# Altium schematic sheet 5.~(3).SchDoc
size 420 x 297 mm
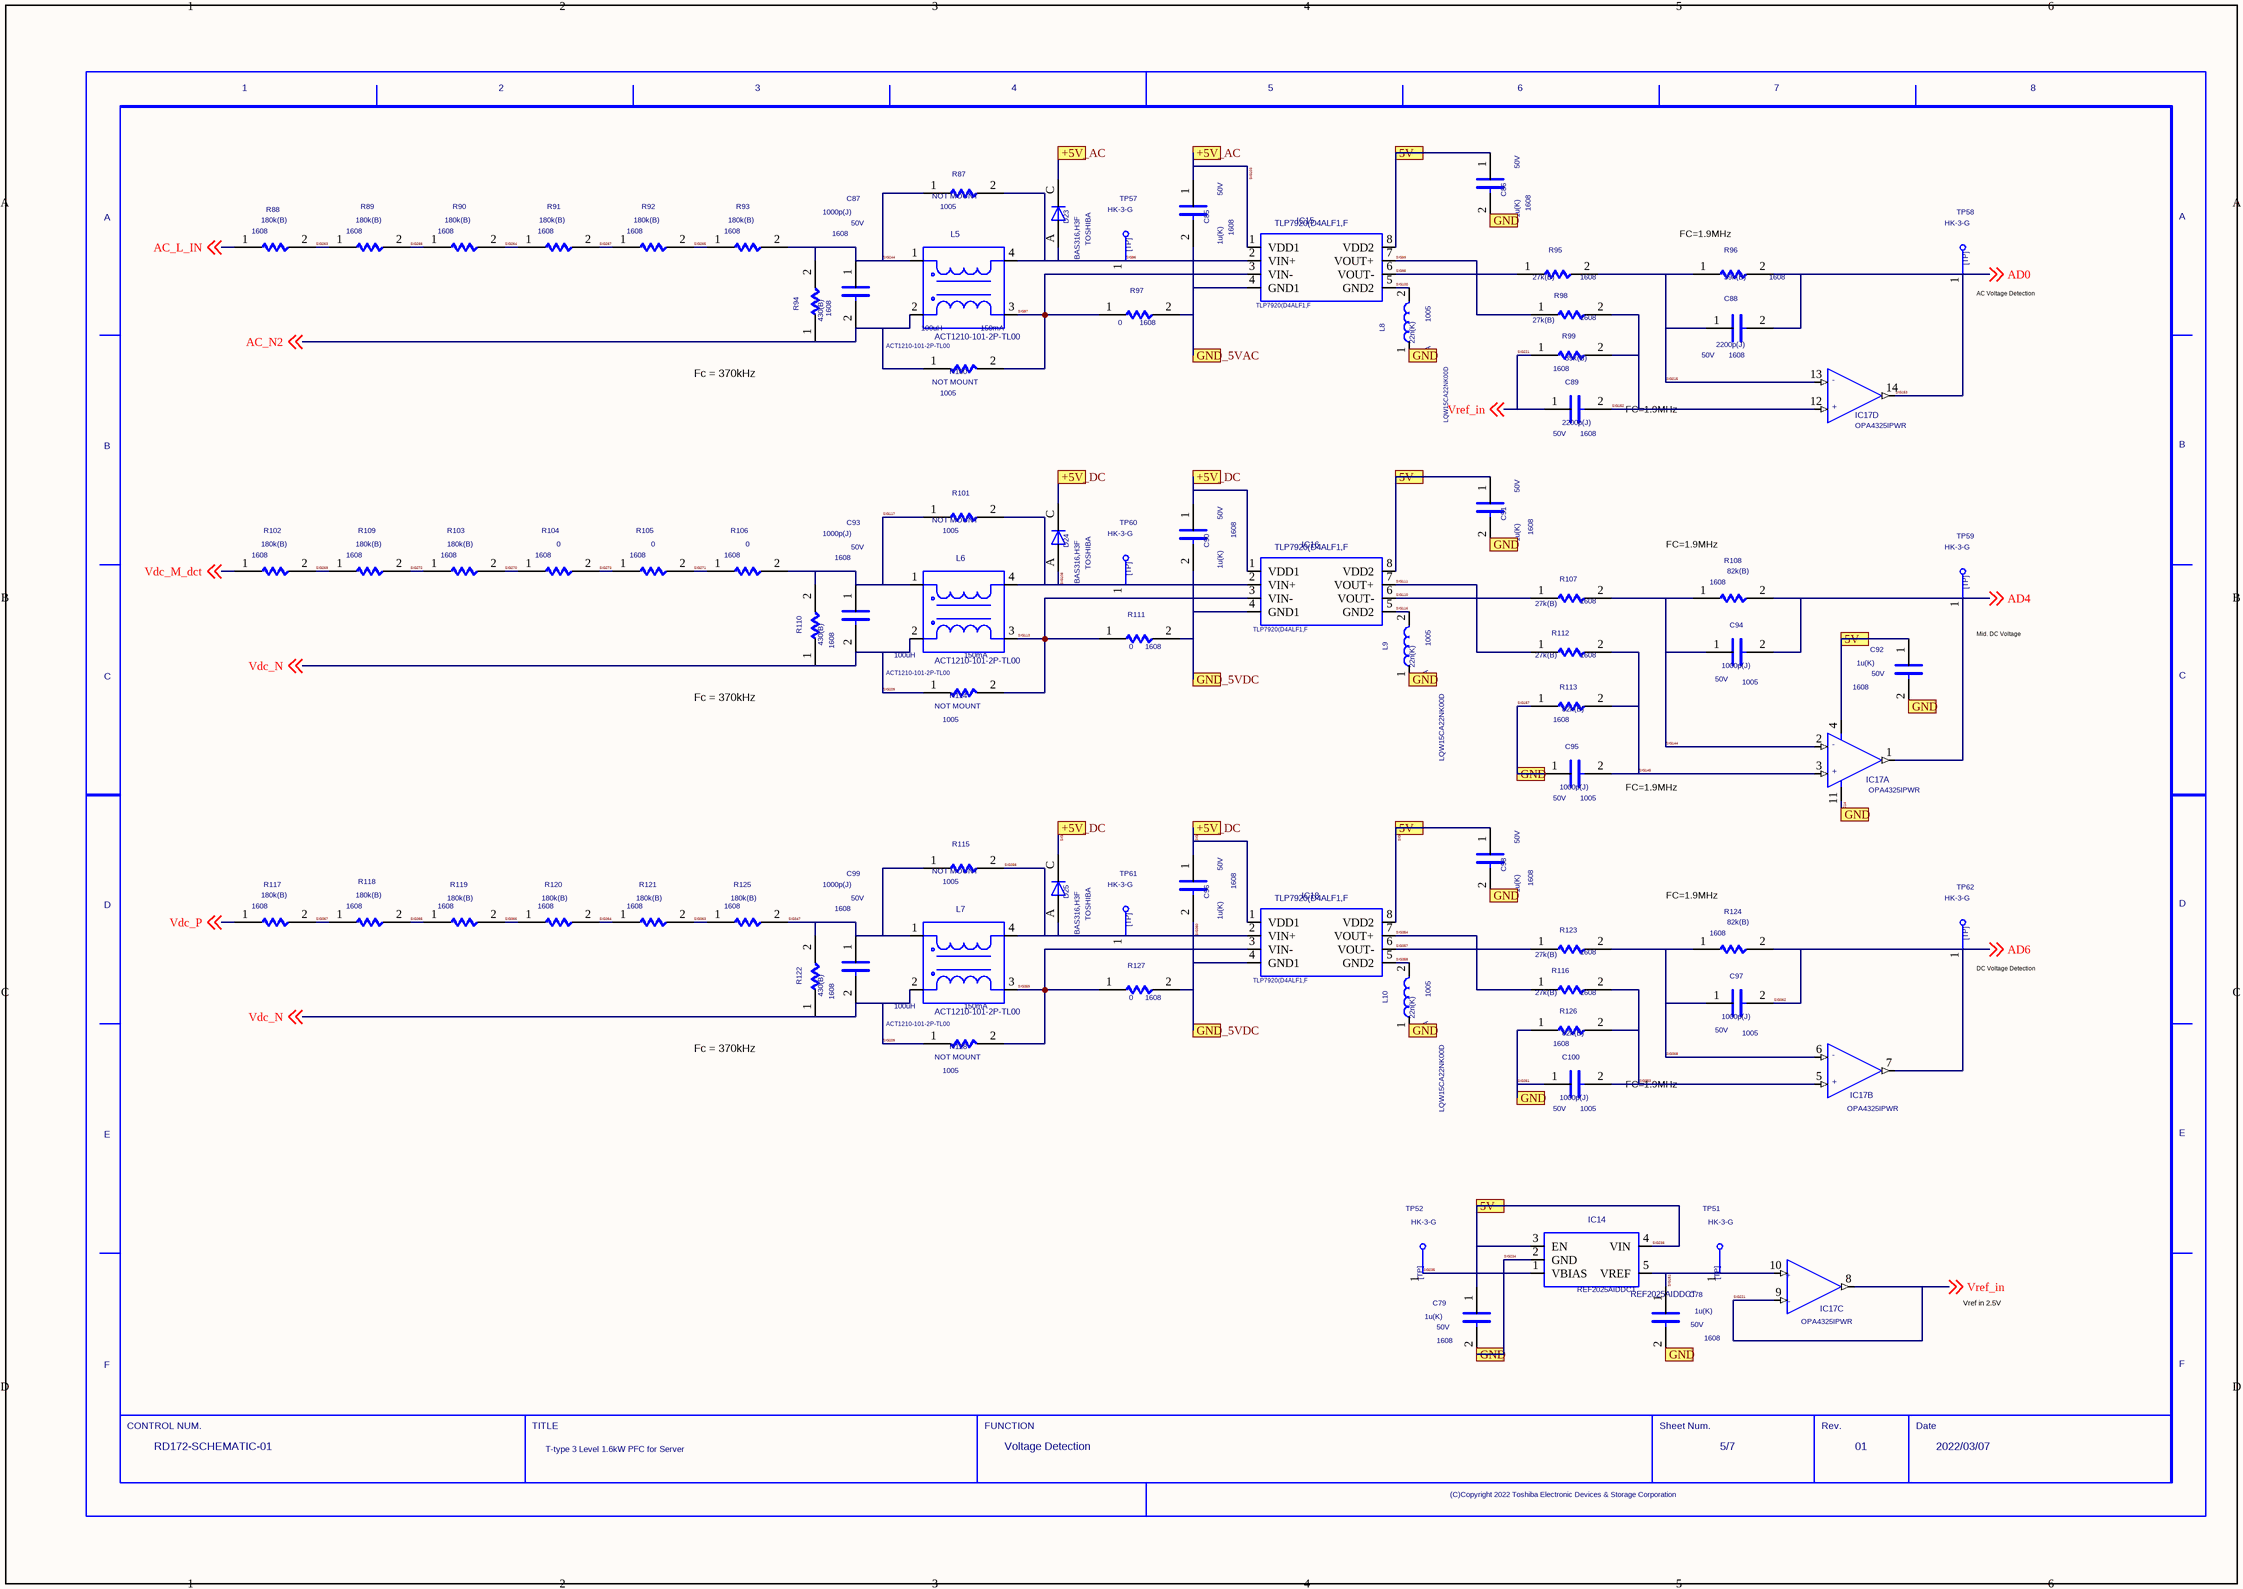
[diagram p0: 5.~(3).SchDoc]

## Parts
C78  SIZECODESMD: 1608  VAL2: 50V  VAL1: 1u(K)  (hidden comment: C)
C79  SIZECODESMD: 1608  VAL2: 50V  VAL1: 1u(K)  (hidden comment: C)
C85  SIZECODESMD: 1608  VAL2: 50V  VAL1: 1u(K)  (hidden comment: C)
C86  SIZECODESMD: 1608  VAL2: 50V  VAL1: 1u(K)  (hidden comment: C)
C87  SIZECODESMD: 1608  VAL2: 50V  VAL1: 1000p(J)  (hidden comment: C)
C88  SIZECODESMD: 1608  VAL2: 50V  VAL1: 2200p(J)  (hidden comment: C)
C89  SIZECODESMD: 1608  VAL2: 50V  VAL1: 2200p(J)  (hidden comment: C)
C90  SIZECODESMD: 1608  VAL2: 50V  VAL1: 1u(K)  (hidden comment: C)
C91  SIZECODESMD: 1608  VAL2: 50V  VAL1: 1u(K)  (hidden comment: C)
C92  SIZECODESMD: 1608  VAL2: 50V  VAL1: 1u(K)  (hidden comment: C)
C93  SIZECODESMD: 1608  VAL2: 50V  VAL1: 1000p(J)  (hidden comment: C)
C94  SIZECODESMD: 1005  VAL2: 50V  VAL1: 1000p(J)  (hidden comment: C)
C95  SIZECODESMD: 1005  VAL2: 50V  VAL1: 1000p(J)  (hidden comment: C)
C96  SIZECODESMD: 1608  VAL2: 50V  VAL1: 1u(K)  (hidden comment: C)
C97  SIZECODESMD: 1005  VAL2: 50V  VAL1: 1000p(J)  (hidden comment: C)
C98  SIZECODESMD: 1608  VAL2: 50V  VAL1: 1u(K)  (hidden comment: C)
C99  SIZECODESMD: 1608  VAL2: 50V  VAL1: 1000p(J)  (hidden comment: C)
C100  SIZECODESMD: 1005  VAL2: 50V  VAL1: 1000p(J)  (hidden comment: C)
D23  USERCOMPTEXT3: TOSHIBA  VAL3: BAS316,H3F  (hidden comment: D)
D24  USERCOMPTEXT3: TOSHIBA  VAL3: BAS316,H3F  (hidden comment: D)
D25  USERCOMPTEXT3: TOSHIBA  VAL3: BAS316,H3F  (hidden comment: D)
IC14  REF2025AIDDCT
IC15  TLP7920(D4ALF1,F
IC16  TLP7920(D4ALF1,F
IC17  VAL3: OPA4325IPWR  (hidden comment: OPA4325IPWR_4)  (parts A,B,C,D of 4)
IC18  TLP7920(D4ALF1,F
L5  ACT1210-101-2P-TL00  VAL1: 100uH
L6  ACT1210-101-2P-TL00  VAL1: 100uH
L7  ACT1210-101-2P-TL00  VAL1: 100uH
L8  VAL3: LQW15CA22NK00D  VAL2: 1.3A  VAL1: 22n(K)  SIZECODESMD: 1005  (hidden comment: L)
L9  VAL3: LQW15CA22NK00D  VAL2: 1.3A  VAL1: 22n(K)  SIZECODESMD: 1005  (hidden comment: L)
L10  VAL3: LQW15CA22NK00D  VAL2: 1.3A  VAL1: 22n(K)  SIZECODESMD: 1005  (hidden comment: L)
R87  SIZECODESMD: 1005  NOTMOUNT: NOT MOUNT  (hidden comment: R)
R88  SIZECODESMD: 1608  VAL1: 180k(B)  (hidden comment: R)
R89  SIZECODESMD: 1608  VAL1: 180k(B)  (hidden comment: R)
R90  SIZECODESMD: 1608  VAL1: 180k(B)  (hidden comment: R)
R91  SIZECODESMD: 1608  VAL1: 180k(B)  (hidden comment: R)
R92  SIZECODESMD: 1608  VAL1: 180k(B)  (hidden comment: R)
R93  SIZECODESMD: 1608  VAL1: 180k(B)  (hidden comment: R)
R94  SIZECODESMD: 1608  VAL1: 430(B)  (hidden comment: R)
R95  SIZECODESMD: 1608  VAL1: 27k(B)  (hidden comment: R)
R96  SIZECODESMD: 1608  VAL1: 39k(B)  (hidden comment: R)
R97  SIZECODESMD: 1608  VAL1: 0  (hidden comment: R)
R98  SIZECODESMD: 1608  VAL1: 27k(B)  (hidden comment: R)
R99  SIZECODESMD: 1608  VAL1: 39k(B)  (hidden comment: R)
R100  SIZECODESMD: 1005  NOTMOUNT: NOT MOUNT  (hidden comment: R)
R101  SIZECODESMD: 1005  NOTMOUNT: NOT MOUNT  (hidden comment: R)
R102  SIZECODESMD: 1608  VAL1: 180k(B)  (hidden comment: R)
R103  SIZECODESMD: 1608  VAL1: 180k(B)  (hidden comment: R)
R104  SIZECODESMD: 1608  VAL1: 0  (hidden comment: R)
R105  SIZECODESMD: 1608  VAL1: 0  (hidden comment: R)
R106  SIZECODESMD: 1608  VAL1: 0  (hidden comment: R)
R107  SIZECODESMD: 1608  VAL1: 27k(B)  (hidden comment: R)
R108  SIZECODESMD: 1608  VAL1: 82k(B)  (hidden comment: R)
R109  SIZECODESMD: 1608  VAL1: 180k(B)  (hidden comment: R)
R110  SIZECODESMD: 1608  VAL1: 430(B)  (hidden comment: R)
R111  SIZECODESMD: 1608  VAL1: 0  (hidden comment: R)
R112  SIZECODESMD: 1608  VAL1: 27k(B)  (hidden comment: R)
R113  SIZECODESMD: 1608  VAL1: 82k(B)  (hidden comment: R)
R114  SIZECODESMD: 1005  NOTMOUNT: NOT MOUNT  (hidden comment: R)
R115  SIZECODESMD: 1005  NOTMOUNT: NOT MOUNT  (hidden comment: R)
R116  SIZECODESMD: 1608  VAL1: 27k(B)  (hidden comment: R)
R117  SIZECODESMD: 1608  VAL1: 180k(B)  (hidden comment: R)
R118  SIZECODESMD: 1608  VAL1: 180k(B)  (hidden comment: R)
R119  SIZECODESMD: 1608  VAL1: 180k(B)  (hidden comment: R)
R120  SIZECODESMD: 1608  VAL1: 180k(B)  (hidden comment: R)
R121  SIZECODESMD: 1608  VAL1: 180k(B)  (hidden comment: R)
R122  SIZECODESMD: 1608  VAL1: 430(B)  (hidden comment: R)
R123  SIZECODESMD: 1608  VAL1: 27k(B)  (hidden comment: R)
R124  SIZECODESMD: 1608  VAL1: 82k(B)  (hidden comment: R)
R125  SIZECODESMD: 1608  VAL1: 180k(B)  (hidden comment: R)
R126  SIZECODESMD: 1608  VAL1: 82k(B)  (hidden comment: R)
R127  SIZECODESMD: 1608  VAL1: 0  (hidden comment: R)
R128  SIZECODESMD: 1005  NOTMOUNT: NOT MOUNT  (hidden comment: R)
TP51  VAL3: HK-3-G  (hidden comment: TP)
TP52  VAL3: HK-3-G  (hidden comment: TP)
TP57  VAL3: HK-3-G  (hidden comment: TP)
TP58  VAL3: HK-3-G  (hidden comment: TP)
TP59  VAL3: HK-3-G  (hidden comment: TP)
TP60  VAL3: HK-3-G  (hidden comment: TP)
TP61  VAL3: HK-3-G  (hidden comment: TP)
TP62  VAL3: HK-3-G  (hidden comment: TP)
U?  DATE: 2022/03/07  REVISION: 01  SHEETNUMBER: 5/7  FUNCTION: Voltage Detection  TITLE: T-type 3 Level 1.6kW PFC for Server  DRAWINGNUMBER: RD172-SCHEMATIC-01  (hidden comment: WAKU_DEF100)

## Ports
5V, +5V_AC, +5V_DC, GND, GND_5VAC, GND_5VDC

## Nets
AC_L_IN: R88.1 ; off-sheet AC_L_IN
AC_N2: C87.2 L5.2 R94.1 R100.1 ; off-sheet AC_N2
AD4: C94.2 IC17.1(OUT) R108.2 TP59.1 ; off-sheet AD4
GND_5VAC: C85.2 IC15.4(GND1) R97.2 ; port GND_5VAC
SIG96: D23.A IC15.2(VIN+) L5.4 R87.2 TP57.1
SIG97: IC15.3(VIN-) L5.3 R97.1 R100.2
SIG98: IC15.6(VOUT-) R95.1
SIG99: IC15.7(VOUT+) R98.1
SIG100: IC15.5(GND2) L8.2
SIG103: C85.1 D23.C IC15.1(VDD1) ; port +5V_AC
SIG108: D24.A IC16.2(VIN+) L6.4 R101.2 TP60.1
SIG110: IC16.6(VOUT-) R107.1
SIG111: IC16.7(VOUT+) R112.1
SIG113: IC16.3(VIN-) L6.3 R111.1 R114.2
SIG116: IC16.5(GND2) L9.2
SIG117: C93.1 L6.1 R101.1 R106.2 R110.2
SIG144: C94.1 IC17.2(IN-) R107.2 R108.1
SIG145: C95.2 IC17.3(IN+) R112.2 R113.2
SIG151: C78.1 IC14.5(VREF) IC17.10 TP51.1
SIG152: C89.2 IC17.12 R98.2 R99.2
SIG153: C88.2 IC17.14 R96.2 TP58.1 ; off-sheet AD0  [also labelled AD0]
SIG157: C78.2 C79.2 C86.2 C91.2 C92.2 C95.1 C98.2 C100.1 IC14.2(GND) IC17.11(V-) L8.1 L9.1 L10.1 R113.1 R126.1 ; port GND  [also labelled SIG214, SIG234, SIG351]
SIG209: C93.2 C99.2 L6.2 L7.2 R110.1 R114.1 R122.1 R128.1 ; off-sheet Vdc_N  [also labelled Vdc_N]
SIG215: C88.1 IC17.13 R95.2 R96.1
SIG221: C89.1 IC17.8 IC17.9 R99.1 ; off-sheet Vref_in  [also labelled Vref_in]
SIG235: IC14.1(VBIAS) TP52.1
SIG236: C79.1 C86.1 C91.1 C92.1 C98.1 IC14.3(EN) IC14.4(VIN) IC15.8(VDD2) IC16.8(VDD2) IC17.4(V+) IC18.8(VDD2) ; port 5V  [also labelled SIG349]
SIG244: C87.1 L5.1 R87.1 R93.2 R94.2
SIG263: R88.2 R89.1
SIG264: R90.2 R91.1
SIG265: R92.2 R93.1
SIG266: R89.2 R90.1
SIG267: R91.2 R92.1
SIG269: R102.2 R109.1
SIG270: R103.2 R104.1
SIG271: R105.2 R106.1
SIG272: R103.1 R109.2
SIG273: R104.2 R105.1
SIG347: C99.1 L7.1 R115.1 R122.2 R125.2
SIG353: C100.2 IC17.5 R116.2 R126.2
SIG354: IC18.7(VOUT+) R116.1
SIG355: C90.1 C96.1 D24.C D25.C IC16.1(VDD1) IC18.1(VDD1) ; port +5V_DC  [also labelled SIG361]
SIG356: D25.A IC18.2(VIN+) L7.4 R115.2 TP61.1
SIG357: IC18.6(VOUT-) R123.1
SIG358: IC18.5(GND2) L10.2
SIG359: IC18.3(VIN-) L7.3 R127.1 R128.2
SIG360: C90.2 C96.2 IC16.4(GND1) IC18.4(GND1) R111.2 R127.2 ; port GND_5VDC
SIG362: C97.2 IC17.7 R124.2 TP62.1 ; off-sheet AD6  [also labelled AD6]
SIG363: R121.2 R125.1
SIG364: R120.2 R121.1
SIG365: R118.2 R119.1
SIG366: R119.2 R120.1
SIG367: R117.2 R118.1
SIG368: C97.1 IC17.6 R123.2 R124.1
Vdc_M_dct: R102.1 ; off-sheet Vdc_M_dct
Vdc_P: R117.1 ; off-sheet Vdc_P

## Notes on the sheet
- (near R96) FC=1.9MHz
- (near TP58) AC Voltage Detection
- Fc = 370kHz
- FC=1.9MHz
- (near R108) FC=1.9MHz
- (near TP59) Mid. DC Voltage
  Detection
- (near C95) FC=1.9MHz
- (near R124) FC=1.9MHz
- (near TP62) DC Voltage Detection
- Vref in 2.5V

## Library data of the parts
C78 C79 C85 C86 C90-C92 C96 C98 = C: OriginalSymbolOrigin: (2540,7620); COMP: -C-UMK107AB7105KA-T
C87 C93 C99 = C: OriginalSymbolOrigin: (2540,7620); COMP: -C-GRM1885C1H102JA01D
C88 C89 = C: OriginalSymbolOrigin: (2540,7620); COMP: -C-GRM1882C1H222JA01D
C94 C95 C97 C100 = C: OriginalSymbolOrigin: (2540,7620); COMP: -C-GRM1555C1H102JA01D
D23-D25 = D: SAVEAREA0: -225,-91,12804,7836; SAVECOUNT: 3; TIME: 14:49:55; UPDATEUSER: 19870035; UPDATETIME: 14:20:16; OriginalSymbolOrigin: (5080,5080); COMP: -D-BAS316_H3F_AC
IC14 = REF2025AIDDCT: Voltage References; MANUFACTURER: Texas Instruments; COMP: -IC-REF2025AIDDCT; TIME: 16:53:54; UPDATEUSER: t5459927; UPDATETIME: 16:09:37; SAVECOUNT: 2; SAVEAREA0: -3467,-13658,20665,4033; OriginalSymbolOrigin: (0,0)
IC15 IC16 IC18 = TLP7920_D4ALF1_F_0: Photocoupler; MANUFACTURER: TOSHIBA; COMP: -IC-TLP7920_LF5_TP5; TIME: 16:53:58; UPDATEUSER: t5459927; UPDATETIME: 16:21:24; SAVECOUNT: 2; SAVEAREA0: -6097,-17212,23397,4411; OriginalSymbolOrigin: (0,0)
IC17 = OPA4325IPWR_4: COMP: -IC-OPA4325IPWR; TIME: 16:31:59; UPDATEUSER: t5459927; UPDATETIME: 16:35:50; SAVECOUNT: 11; SAVEAREA0: -17633,-13280,32685,23610; OriginalSymbolOrigin: (2540,10160); CaptureCellPackProp: OPA4325IPWR_4A; FUNCN: OPA4325IPWR_1
L5-L7 = ACT1210_101_2P_TL00: 150mA; MAKER: TDK; COMP: -L-ACT1210-101-2P-TL00; TIME: 16:53:54; UPDATEUSER: t5459927; SAVECOUNT: 1; SAVEAREA0: -3836,-15544,18528,852; OriginalSymbolOrigin: (0,0); INSTANCENAME: INS18165735
L8-L10 = L: OriginalSymbolOrigin: (2540,5080); COMP: -L-LQW15CA22NK00
R87 R100 R101 R114 R115 R128 = R: OriginalSymbolOrigin: (5080,5080); COMP: -R-NC_R1005
R88-R93 R102 R103 R109 R117-R121 R125 = R: OriginalSymbolOrigin: (5080,5080); COMP: -R-ERA3AEB184V; VAL2: 100mW
R94 R110 R122 = R: OriginalSymbolOrigin: (5080,5080); COMP: -R-ERA3AEB431V; VAL2: 100mW
R95 R98 R107 R112 R116 R123 = R: OriginalSymbolOrigin: (5080,5080); COMP: -R-ERA3ARB273V; VAL2: 100mW
R96 R99 = R: OriginalSymbolOrigin: (5080,5080); COMP: -R-ERA3AEB393V; VAL2: 100mW
R97 R104-R106 R111 R127 = R: OriginalSymbolOrigin: (5080,5080); COMP: -R-RK73Z1JTTD; VAL2: 1A
R108 R113 R124 R126 = R: OriginalSymbolOrigin: (5080,5080); COMP: -R-ERA3ARB823V; VAL2: 100mW
TP51 TP52 TP57-TP62 = TP: TIME: 16:12:21; UPDATEUSER: fukuda-y; UPDATETIME: 16:18:11; SAVECOUNT: 2; SAVEAREA0: -242,-92,12810,7836; OriginalSymbolOrigin: (0,7620); COMP: -TP-HK-3-G
U? = WAKU_DEF100: PLOTTIME: HH:MM; SAVEAREA0: 148187,-66180,486823,89919; TIME: 14:30:25; UPDATEUSER: t5459927; UPDATETIME: 09:34:23; SAVECOUNT: 6; OriginalSymbolOrigin: (10160,284480)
